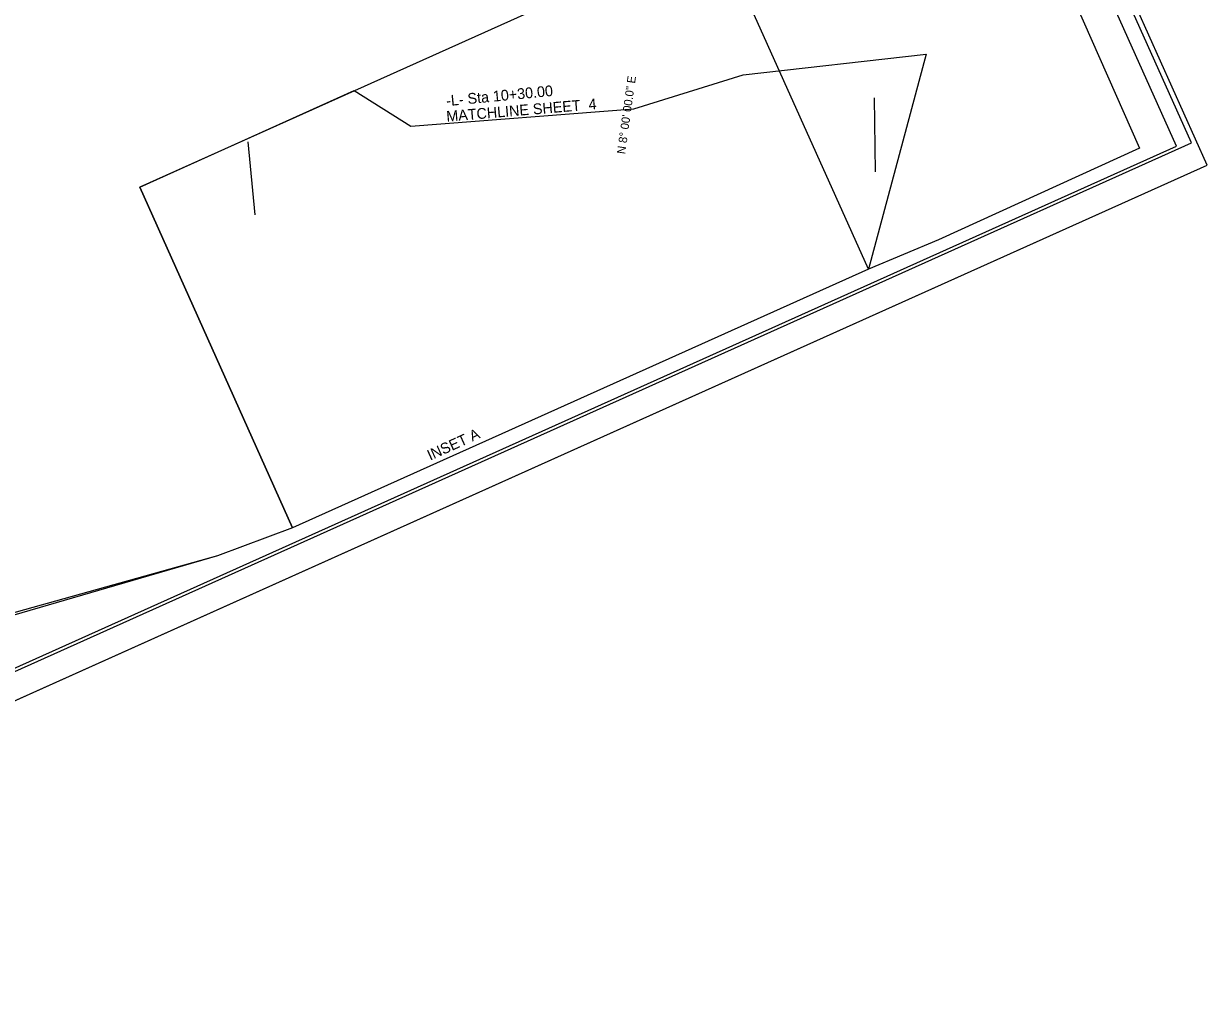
# Model space of a CAD drawing. Extents: x 553939 to 555925, y 502653 to 504347.
# Drawn here: x 554932 to 555925, y 502653 to 503462 of the extents above; entities that cross this region are included whole.
import ezdxf

# ---------------------------------------------------------------- set-up
doc = ezdxf.new("R2010")
doc.units = 0
for name, color, linetype in [('Matchline', 7, 'Continuous'), ('Matchline Text', 7, 'Continuous'), ('Prop EOT', 7, 'Continuous'), ('Prop Horizontal Alignment Direction Label', 7, 'Continuous'), ('Sheet Border Standard 30in CELL', 7, 'Continuous'), ('Sheet Clip Boundary CELL', 7, 'Continuous'), ('Sheet Cutting Line CELL', 7, 'Continuous'), ('Sheet Plot Border Inside CELL', 7, 'Continuous'), ('Sheet Plot Border Outside CELL', 7, 'Continuous')]:
    doc.layers.add(name, color=color, linetype=linetype)

msp = doc.modelspace()

# ---------------------------------------------------------------- linework, layer by layer
at = {"layer": 'Matchline'}
msp.add_lwpolyline([(555029.44, 503324.56), (555209.51, 503405.63), (555257.02, 503375.83), (555444.22, 503390.39), (555535.81, 503418.99), (555689.44, 503436.13), (555640.99, 503255.83), (555157.75, 503038.83)], close=True, dxfattribs=at)
at = {"layer": 'Prop EOT'}
for p, q in [((555646.89, 503337.47), (555646.14, 503399.43)), ((555120.22, 503362.73), (555125.96, 503301.27))]:
    msp.add_line(p, q, dxfattribs=at)
at = {"layer": 'Sheet Border Standard 30in CELL'}
msp.add_lwpolyline([(555469.6, 504316.85), (554101.23, 503702.4), (554531.34, 502744.54), (555899.72, 503358.98)], close=True, dxfattribs=at)
at = {"layer": 'Sheet Clip Boundary CELL'}
for points in [[(554122.43, 503695.68), (555128.42, 504154.2), (555095.7, 504120), (555113.65, 504088.12), (555364.03, 504064.84), (555538.05, 504147.98), (555542.54, 504077.37), (555561.42, 504000.98), (555608.35, 503927.62), (555814.87, 503478.7), (555868.57, 503357.36), (555699.98, 503280.3), (555640.99, 503255.83), (555512.69, 503541.56), (555029.44, 503324.56), (555157.75, 503038.83), (555094.66, 503015.3), (554759.27, 502917.8)], [(554122.43, 503695.68), (555128.42, 504154.2), (555095.7, 504120), (555113.65, 504088.12), (555364.03, 504064.84), (555538.05, 504147.98), (555542.54, 504077.37), (555561.42, 504000.98), (555610.11, 503951.13), (555644.95, 503906.87), (555662.42, 503867.97), (555642.54, 503853.07), (555814.87, 503478.7), (555868.57, 503357.36), (555699.98, 503280.3), (555640.99, 503255.83), (555512.69, 503541.56), (555029.44, 503324.56), (555157.75, 503038.83), (555094.66, 503015.3), (554864.55, 502951)]]:
    msp.add_lwpolyline(points, dxfattribs=at)
at = {"layer": 'Sheet Cutting Line CELL'}
msp.add_line((554389.23, 502653.32), (555925.47, 503343.14), dxfattribs=at)
at = {"layer": 'Sheet Plot Border Inside CELL'}
msp.add_lwpolyline([(555479.96, 504324.29), (553959.7, 503641.65), (554391.9, 502679.13), (555912.16, 503361.78)], close=True, dxfattribs=at)
at = {"layer": 'Sheet Plot Border Outside CELL'}
msp.add_lwpolyline([(555474.87, 504346.62), (553938.64, 503656.8), (554389.23, 502653.32), (555925.47, 503343.14)], close=True, dxfattribs=at)

# ---------------------------------------------------------------- texts
at = {"layer": 'Matchline Text'}
for s, rotation, p in [('  -L- Sta 10+30.00', 5.53151, (555280.38, 503391.89)), ('MATCHLINE SHEET  4', 4.77471, (555287.15, 503379.51)), (' INSET A', 24.40842, (555270.18, 503093.7))]:
    msp.add_text(s, height=9, rotation=rotation, dxfattribs=at).set_placement(p)
at = {"layer": 'Prop Horizontal Alignment Direction Label'}
msp.add_text('N 8%%d 00\' 00.0" E', height=7, rotation=82, dxfattribs=at).set_placement((555436.79, 503352.02))

doc.saveas('drawing.dxf')
